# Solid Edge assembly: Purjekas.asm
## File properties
Author: Administrator
Template: Normal.asm
Last saved by: Administrator
Revision: 27
Application: Solid Edge
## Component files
Purjekas.par
Kajut.par
uks.par
mast.par
aken.par
katusealune.psm
kuppel.par
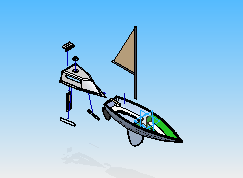
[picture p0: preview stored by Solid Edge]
